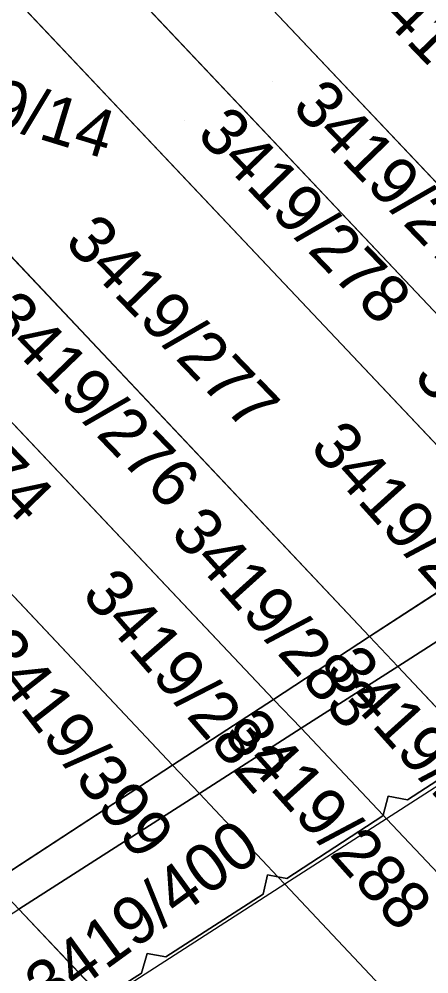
# Model space of a CAD drawing. Extents: x -262715 to -259381, y -1237238 to -1231182.
# Drawn here: x -261985.94 to -261968.79, y -1235718.42 to -1235678.51 of the extents above; entities that cross this region are included whole.
import ezdxf

# ---------------------------------------------------------------- set-up
doc = ezdxf.new("R2010")
doc.units = 0
for name, color, linetype in [('body_kn', 7, 'Continuous'), ('kladpar_druhypozemkov', 7, 'Continuous'), ('kladpar_hranice', 7, 'Continuous'), ('kladpar_parcelnecisla', 7, 'Continuous'), ('kladpar_plochy', 7, 'Continuous'), ('zappar_hrandruhpozemk', 7, 'Continuous')]:
    doc.layers.add(name, color=color, linetype=linetype)

msp = doc.modelspace()

# ---------------------------------------------------------------- linework, layer by layer
at = {"layer": 'body_kn'}
for p, q in [((-261971.28, -1235704.32), (-261971.28, -1235704.32)), ((-261971.28, -1235704.32), (-261971.28, -1235704.32)), ((-261970.1, -1235705.57), (-261970.1, -1235705.57)), ((-261970.1, -1235705.57), (-261970.1, -1235705.57)), ((-261975.29, -1235706.94), (-261975.29, -1235706.94)), ((-261975.29, -1235706.94), (-261975.29, -1235706.94)), ((-261974.14, -1235708.15), (-261974.14, -1235708.15)), ((-261979.52, -1235709.69), (-261979.52, -1235709.69)), ((-261979.52, -1235709.69), (-261979.52, -1235709.69)), ((-261978.39, -1235710.88), (-261978.39, -1235710.88)), ((-261978.39, -1235710.88), (-261978.39, -1235710.88)), ((-261970.5, -1235710.99), (-261970.5, -1235710.99)), ((-261969.69, -1235711.14), (-261969.69, -1235711.14)), ((-261970.72, -1235711.81), (-261970.72, -1235711.81)), ((-261970.71, -1235711.78), (-261970.71, -1235711.78)), ((-261970.71, -1235711.78), (-261970.71, -1235711.78)), ((-261970.57, -1235711.93), (-261970.57, -1235711.93)), ((-261975.55, -1235714.28), (-261975.55, -1235714.28)), ((-261975.11, -1235714.36), (-261975.11, -1235714.36)), ((-261974.82, -1235714.67), (-261974.82, -1235714.67)), ((-261974.74, -1235714.43), (-261974.74, -1235714.43)), ((-261975.73, -1235715.08), (-261975.73, -1235715.08)), ((-261980.58, -1235717.56), (-261980.58, -1235717.56)), ((-261979.8, -1235717.71), (-261979.8, -1235717.71)), ((-261980.82, -1235718.38), (-261980.82, -1235718.38))]:
    msp.add_line(p, q, dxfattribs=at)
at = {"layer": 'kladpar_druhypozemkov'}
for p, q in [((-261975.35, -1235681.12), (-261975.35, -1235681.12)), ((-261979.01, -1235682.75), (-261979.01, -1235682.75)), ((-261978.31, -1235691.05), (-261978.31, -1235691.05)), ((-261971.7, -1235705.75), (-261971.7, -1235705.75)), ((-261969.08, -1235707.87), (-261969.08, -1235707.87)), ((-261975.76, -1235708.4), (-261975.76, -1235708.4)), ((-261973.09, -1235711.07), (-261973.09, -1235711.07)), ((-261980.94, -1235711.66), (-261980.94, -1235711.66)), ((-261981.11, -1235715.23), (-261981.11, -1235715.23))]:
    msp.add_line(p, q, dxfattribs=at)
at = {"layer": 'kladpar_hranice'}
for p, q in [((-261961.64, -1235698.05), (-261987.3, -1235670.92)), ((-261987.3, -1235670.92), (-261961.64, -1235698.05)), ((-261981.7, -1235671.38), (-261958.43, -1235695.96)), ((-261958.43, -1235695.96), (-261981.7, -1235671.38)), ((-261964.85, -1235700.14), (-261989.83, -1235673.71)), ((-261989.83, -1235673.71), (-261964.85, -1235700.14)), ((-261971.28, -1235704.32), (-261992.01, -1235682.36)), ((-261992.01, -1235682.36), (-261971.28, -1235704.32)), ((-261975.29, -1235706.94), (-261998.1, -1235682.84)), ((-261998.1, -1235682.84), (-261975.29, -1235706.94)), ((-261979.52, -1235709.69), (-262001.4, -1235686.48)), ((-262001.4, -1235686.48), (-261979.52, -1235709.69)), ((-261971.28, -1235704.32), (-261964.85, -1235700.14)), ((-261964.85, -1235700.14), (-261971.28, -1235704.32)), ((-261970.1, -1235705.57), (-261963.63, -1235701.43)), ((-261963.63, -1235701.43), (-261970.1, -1235705.57)), ((-261975.29, -1235706.94), (-261971.28, -1235704.32)), ((-261971.28, -1235704.32), (-261975.29, -1235706.94)), ((-261970.1, -1235705.57), (-261971.28, -1235704.32)), ((-261971.28, -1235704.32), (-261970.1, -1235705.57)), ((-261974.14, -1235708.15), (-261970.1, -1235705.57)), ((-261970.1, -1235705.57), (-261974.14, -1235708.15)), ((-261966.68, -1235709.19), (-261970.1, -1235705.57)), ((-261970.1, -1235705.57), (-261966.68, -1235709.19)), ((-261979.52, -1235709.69), (-261975.29, -1235706.94)), ((-261975.29, -1235706.94), (-261979.52, -1235709.69)), ((-261974.14, -1235708.15), (-261975.29, -1235706.94)), ((-261975.29, -1235706.94), (-261974.14, -1235708.15)), ((-261978.39, -1235710.88), (-261974.14, -1235708.15)), ((-261974.14, -1235708.15), (-261978.39, -1235710.88)), ((-261970.71, -1235711.78), (-261974.14, -1235708.15)), ((-261974.14, -1235708.15), (-261970.71, -1235711.78)), ((-261979.52, -1235709.69), (-261987.03, -1235714.58)), ((-261987.03, -1235714.58), (-261979.52, -1235709.69)), ((-261978.39, -1235710.88), (-261979.52, -1235709.69)), ((-261979.52, -1235709.69), (-261978.39, -1235710.88)), ((-261985.95, -1235715.71), (-261978.39, -1235710.88)), ((-261978.39, -1235710.88), (-261985.95, -1235715.71)), ((-261975.11, -1235714.36), (-261978.39, -1235710.88)), ((-261978.39, -1235710.88), (-261975.11, -1235714.36)), ((-261982.44, -1235719.42), (-261985.95, -1235715.71)), ((-261985.95, -1235715.71), (-261982.44, -1235719.42))]:
    msp.add_line(p, q, dxfattribs=at)
for points in [[(-261970.71, -1235711.78), (-261970.5, -1235710.99), (-261969.69, -1235711.14), (-261966.68, -1235709.19)], [(-261966.68, -1235709.19), (-261969.69, -1235711.14), (-261970.5, -1235710.99), (-261970.71, -1235711.78)], [(-261975.11, -1235714.36), (-261974.74, -1235714.43), (-261970.72, -1235711.81), (-261970.71, -1235711.78)], [(-261970.71, -1235711.78), (-261970.72, -1235711.81), (-261974.74, -1235714.43), (-261975.11, -1235714.36)], [(-261955.68, -1235727.67), (-261970.57, -1235711.93), (-261970.71, -1235711.78)], [(-261970.71, -1235711.78), (-261970.57, -1235711.93), (-261955.68, -1235727.67)], [(-261982.44, -1235719.42), (-261980.82, -1235718.38), (-261980.58, -1235717.56), (-261979.8, -1235717.71), (-261975.73, -1235715.08), (-261975.55, -1235714.28), (-261975.11, -1235714.36)], [(-261975.11, -1235714.36), (-261975.55, -1235714.28), (-261975.73, -1235715.08), (-261979.8, -1235717.71), (-261980.58, -1235717.56), (-261980.82, -1235718.38), (-261982.44, -1235719.42)], [(-261959.95, -1235730.45), (-261974.82, -1235714.67), (-261975.11, -1235714.36)], [(-261975.11, -1235714.36), (-261974.82, -1235714.67), (-261959.95, -1235730.45)]]:
    msp.add_lwpolyline(points, dxfattribs=at)
at = {"layer": 'kladpar_plochy'}
for points in [[(-261981.7, -1235671.38), (-261980.24, -1235670.22), (-261977.29, -1235667.16), (-261980.69, -1235666.4), (-261982.74, -1235667.31), (-261983.8, -1235669.16), (-261984.77, -1235668.13), (-261978.42, -1235661.13), (-261950.46, -1235690.77), (-261958.43, -1235695.96)], [(-261958.43, -1235695.96), (-261961.64, -1235698.05), (-261987.3, -1235670.92), (-261984.77, -1235668.13), (-261983.8, -1235669.16), (-261984.81, -1235670.92), (-261984.32, -1235673.45), (-261981.7, -1235671.38)], [(-261961.64, -1235698.05), (-261964.85, -1235700.14), (-261989.83, -1235673.71), (-261987.3, -1235670.92)], [(-261964.85, -1235700.14), (-261971.28, -1235704.32), (-261992.01, -1235682.36), (-261991.47, -1235681.87), (-261988.22, -1235678.49), (-261991.05, -1235677.62), (-261994.25, -1235679.21), (-261994.53, -1235679.69), (-261994.9, -1235679.3), (-261989.83, -1235673.71)], [(-261971.28, -1235704.32), (-261975.29, -1235706.94), (-261998.1, -1235682.84), (-261994.9, -1235679.3), (-261994.53, -1235679.69), (-261995.89, -1235681.97), (-261994.95, -1235684.98), (-261992.01, -1235682.36)], [(-261975.29, -1235706.94), (-261979.52, -1235709.69), (-262001.4, -1235686.48), (-261998.1, -1235682.84)], [(-261979.52, -1235709.69), (-261987.03, -1235714.58), (-261997.74, -1235703.27), (-262003.61, -1235694.38), (-262000.6, -1235691.28), (-262003.06, -1235690.37), (-262005.91, -1235691.45), (-262001.4, -1235686.48)], [(-262009.61, -1235700.5), (-262009.43, -1235697.67), (-262008.41, -1235694.54), (-262007.31, -1235693.18), (-262004.88, -1235695.73), (-262005.08, -1235695.94), (-261989.99, -1235718.38), (-261988.73, -1235717.49), (-261985.95, -1235715.71), (-261982.44, -1235719.42), (-261984.75, -1235720.91), (-261984.96, -1235720.59), (-261986.19, -1235721.34), (-261986.78, -1235721.7), (-261987.43, -1235722.19), (-261976.08, -1235739.49), (-261988.19, -1235726.57), (-262005.64, -1235700.02), (-262009.36, -1235700.47)], [(-261963.63, -1235701.43), (-261970.1, -1235705.57), (-261971.28, -1235704.32), (-261964.85, -1235700.14)], [(-261960.51, -1235704.73), (-261960.68, -1235705.31), (-261964.65, -1235707.88), (-261965.5, -1235707.71), (-261965.68, -1235708.55), (-261966.68, -1235709.19), (-261970.1, -1235705.57), (-261963.63, -1235701.43)], [(-261970.1, -1235705.57), (-261974.14, -1235708.15), (-261975.29, -1235706.94), (-261971.28, -1235704.32)], [(-261966.68, -1235709.19), (-261969.69, -1235711.14), (-261970.5, -1235710.99), (-261970.71, -1235711.78), (-261974.14, -1235708.15), (-261970.1, -1235705.57)], [(-261979.52, -1235709.69), (-261975.29, -1235706.94), (-261974.14, -1235708.15), (-261978.39, -1235710.88)], [(-261970.71, -1235711.78), (-261970.72, -1235711.81), (-261974.74, -1235714.43), (-261975.11, -1235714.36), (-261978.39, -1235710.88), (-261974.14, -1235708.15)], [(-261966.68, -1235709.19), (-261966.54, -1235709.34), (-261953.19, -1235723.48), (-261954.49, -1235724.32), (-261953.31, -1235726.12), (-261955.68, -1235727.67), (-261970.57, -1235711.93), (-261970.71, -1235711.78), (-261970.5, -1235710.99), (-261969.69, -1235711.14)], [(-261978.39, -1235710.88), (-261985.95, -1235715.71), (-261987.03, -1235714.58), (-261979.52, -1235709.69)], [(-261982.44, -1235719.42), (-261985.95, -1235715.71), (-261978.39, -1235710.88), (-261975.11, -1235714.36), (-261975.55, -1235714.28), (-261975.73, -1235715.08), (-261979.8, -1235717.71), (-261980.58, -1235717.56), (-261980.82, -1235718.38)], [(-261970.71, -1235711.78), (-261970.57, -1235711.93), (-261955.68, -1235727.67), (-261959.95, -1235730.45), (-261974.82, -1235714.67), (-261975.11, -1235714.36), (-261974.74, -1235714.43), (-261970.72, -1235711.81)], [(-261982.44, -1235719.42), (-261980.82, -1235718.38), (-261980.58, -1235717.56), (-261979.8, -1235717.71), (-261975.73, -1235715.08), (-261975.55, -1235714.28), (-261975.11, -1235714.36), (-261974.82, -1235714.67), (-261959.95, -1235730.45), (-261967.39, -1235735.31), (-261982.35, -1235719.52)]]:
    msp.add_lwpolyline(points, close=True, dxfattribs=at)
at = {"layer": 'zappar_hrandruhpozemk'}
msp.add_lwpolyline([(-261952.6, -1235700.36), (-261953.64, -1235701.03), (-261956.86, -1235703.1), (-261960.09, -1235705.18), (-261966.54, -1235709.34), (-261970.57, -1235711.93), (-261974.82, -1235714.67), (-261982.35, -1235719.52), (-261985.91, -1235721.81)], dxfattribs=at)

# ---------------------------------------------------------------- texts
at = {"layer": 'kladpar_parcelnecisla'}
for s, rotation, p in [('3419/281', 314, (-261971.869, -1235677.32)), ('3419/14', 343, (-261991.591, -1235681.531)), ('3419/279', 314, (-261974.579, -1235682.232)), ('3419/278', 314, (-261978.566, -1235683.375)), ('3419/277', 314, (-261984.096, -1235687.876)), ('3419/276', 314, (-261987.419, -1235691.072)), ('3419/274', 314, (-261993.549, -1235691.652)), ('3419/285', 312, (-261969.484, -1235693.499)), ('3419/284', 312, (-261973.827, -1235696.45)), ('3419/283', 312, (-261979.666, -1235700.034)), ('3419/282', 311, (-261983.373, -1235702.589)), ('3419/399', 308, (-261987.776, -1235704.967)), ('3419/289', 312, (-261973.217, -1235705.82)), ('3419/288', 312, (-261977.473, -1235708.452)), ('3419/400', 36, (-261984.73, -1235720.02))]:
    msp.add_text(s, height=2, rotation=rotation, dxfattribs=at).set_placement(p)

doc.saveas('drawing.dxf')
